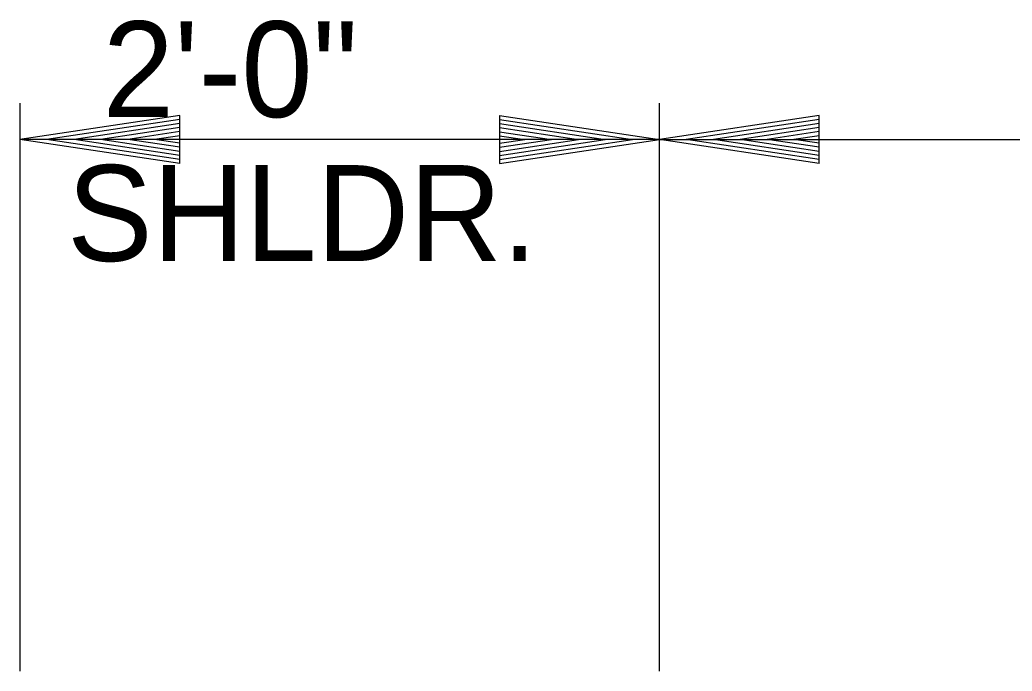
# Model space of a CAD drawing. Extents: x 3575 to 11445, y 9479 to 13278.
# Drawn here: x 6844.8 to 6906.9, y 10496.9 to 10537.7 of the extents above; entities that cross this region are included whole.
import ezdxf

# ---------------------------------------------------------------- set-up
doc = ezdxf.new("R2010")
doc.units = 0
doc.layers.add('R_Dimension', color=7, linetype='Continuous')

msp = doc.modelspace()

# ---------------------------------------------------------------- linework, layer by layer
at = {"layer": 'R_Dimension'}
for p, q in [((6844.803, 10532.461), (6844.803, 10496.92)), ((6884.803, 10496.92), (6884.803, 10532.461)), ((6854.803, 10531.69), (6844.803, 10530.19)), ((6854.803, 10528.69), (6854.803, 10531.69)), ((6874.803, 10531.69), (6884.803, 10530.19)), ((6874.803, 10531.69), (6874.803, 10528.69)), ((6894.803, 10531.69), (6884.803, 10530.19)), ((6894.803, 10528.69), (6894.803, 10531.69)), ((6854.803, 10531.44), (6846.473, 10530.19)), ((6854.803, 10531.185), (6848.193, 10530.19)), ((6874.803, 10531.44), (6883.133, 10530.19)), ((6874.803, 10531.185), (6881.413, 10530.19)), ((6894.803, 10531.44), (6886.473, 10530.19)), ((6894.803, 10531.185), (6888.193, 10530.19)), ((6854.803, 10530.935), (6849.858, 10530.19)), ((6854.803, 10530.68), (6851.553, 10530.19)), ((6854.803, 10530.425), (6853.223, 10530.19)), ((6874.803, 10530.935), (6879.748, 10530.19)), ((6874.803, 10530.675), (6878.053, 10530.19)), ((6874.803, 10530.425), (6876.383, 10530.19)), ((6894.803, 10530.935), (6889.858, 10530.19)), ((6894.803, 10530.68), (6891.553, 10530.19)), ((6894.803, 10530.425), (6893.223, 10530.19)), ((6854.803, 10528.69), (6844.803, 10530.19)), ((6884.803, 10530.19), (6844.803, 10530.19)), ((6854.803, 10528.94), (6846.473, 10530.19)), ((6854.803, 10529.195), (6848.193, 10530.19)), ((6854.803, 10529.445), (6849.858, 10530.19)), ((6854.803, 10529.705), (6851.553, 10530.19)), ((6854.803, 10529.955), (6853.223, 10530.19)), ((6874.803, 10528.69), (6884.803, 10530.19)), ((6874.803, 10529.7), (6878.053, 10530.19)), ((6874.803, 10529.195), (6881.413, 10530.19)), ((6874.803, 10528.94), (6883.133, 10530.19)), ((6874.803, 10529.445), (6879.748, 10530.19)), ((6874.803, 10529.955), (6876.383, 10530.19)), ((6894.803, 10528.69), (6884.803, 10530.19)), ((6884.803, 10530.19), (7104.803, 10530.19)), ((6894.803, 10528.94), (6886.473, 10530.19)), ((6894.803, 10529.195), (6888.193, 10530.19)), ((6894.803, 10529.445), (6889.858, 10530.19)), ((6894.803, 10529.705), (6891.553, 10530.19)), ((6894.803, 10529.955), (6893.223, 10530.19))]:
    msp.add_line(p, q, dxfattribs=at)

# ---------------------------------------------------------------- texts
for s, p in [(' 2\'-0"', (6847.757, 10531.588)), ('SHLDR.', (6847.757, 10522.588))]:
    msp.add_text(s, height=6, dxfattribs=at).set_placement(p)

doc.saveas('drawing.dxf')
